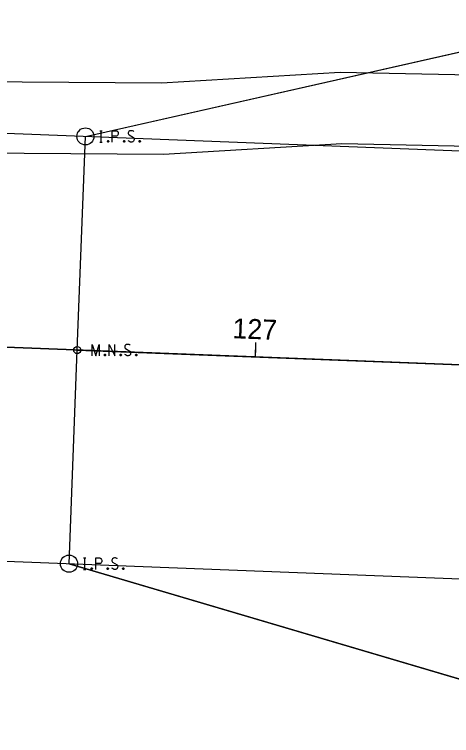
# Model space of a CAD drawing. Extents: x 2003596 to 2006933, y 570827 to 573780.
# Drawn here: x 2005400.5 to 2005461.8, y 572566.7 to 572667.9 of the extents above; entities that cross this region are included whole.
import ezdxf

# ---------------------------------------------------------------- set-up
doc = ezdxf.new("R2010")
doc.units = 0
for name, color, linetype in [('DT_X_Contour_Major', 7, 'Continuous'), ('DT_X_Spot_Elev', 7, 'Continuous'), ('GE_X_Alignment', 7, 'Continuous'), ('GE_X_Alignment_100_Stations', 7, 'Continuous'), ('GE_X_Alignment_500_Stations', 7, 'Continuous'), ('RW_X_CL', 7, 'Continuous'), ('RW_X_Esmt_SH', 7, 'Continuous'), ('SV_P_Mon_Cells_Set', 7, 'Continuous'), ('UT_X_Overhead_Electric', 7, 'Continuous'), ('UT_X_Overhead_Telecom', 7, 'Continuous'), ('UT_X_Telecom', 7, 'Continuous')]:
    doc.layers.add(name, color=color, linetype=linetype)

msp = doc.modelspace()

# ---------------------------------------------------------------- linework, layer by layer
at = {"layer": 'DT_X_Contour_Major'}
for points in [[(2005411.36, 572620.02), (2005411.36, 572621.62), (2005411.87, 572620.02), (2005412.36, 572621.62), (2005412.36, 572620.02)], [(2005413.73, 572620.02), (2005413.73, 572621.62), (2005414.56, 572620.02), (2005414.56, 572621.62)], [(2005416.71, 572621.51), (2005416.69, 572621.53), (2005416.65, 572621.56), (2005416.56, 572621.6), (2005416.43, 572621.62), (2005416.35, 572621.62), (2005416.31, 572621.62), (2005416.17, 572621.58), (2005416.05, 572621.51), (2005415.97, 572621.41), (2005415.95, 572621.31), (2005415.95, 572621.23), (2005415.97, 572621.13), (2005416.06, 572621.04), (2005416.67, 572620.67), (2005416.72, 572620.62), (2005416.74, 572620.56), (2005416.76, 572620.49), (2005416.76, 572620.41), (2005416.75, 572620.34), (2005416.74, 572620.29), (2005416.72, 572620.22), (2005416.7, 572620.17), (2005416.68, 572620.14), (2005416.64, 572620.1), (2005416.61, 572620.07), (2005416.57, 572620.05), (2005416.53, 572620.04), (2005416.43, 572620.02), (2005416.28, 572620.02), (2005416.18, 572620.05), (2005416.04, 572620.14), (2005415.95, 572620.21)], [(2005413.13, 572620.24), (2005413.18, 572620.24), (2005413.22, 572620.21), (2005413.25, 572620.16), (2005413.25, 572620.1), (2005413.22, 572620.05), (2005413.18, 572620.02), (2005413.13, 572620.02), (2005413.09, 572620.05), (2005413.06, 572620.1), (2005413.06, 572620.16), (2005413.09, 572620.21), (2005413.13, 572620.24)], [(2005415.34, 572620.24), (2005415.4, 572620.24), (2005415.43, 572620.21), (2005415.46, 572620.16), (2005415.46, 572620.1), (2005415.43, 572620.05), (2005415.4, 572620.02), (2005415.34, 572620.02), (2005415.31, 572620.05), (2005415.28, 572620.1), (2005415.28, 572620.16), (2005415.31, 572620.21), (2005415.34, 572620.24)], [(2005417.53, 572620.24), (2005417.58, 572620.24), (2005417.61, 572620.21), (2005417.65, 572620.16), (2005417.65, 572620.1), (2005417.61, 572620.05), (2005417.58, 572620.02), (2005417.53, 572620.02), (2005417.49, 572620.05), (2005417.46, 572620.1), (2005417.46, 572620.16), (2005417.49, 572620.21), (2005417.53, 572620.24)]]:
    msp.add_lwpolyline(points, dxfattribs=at)
msp.add_circle((2005409.27, 572620.82), 0.497, dxfattribs=at)
at = {"layer": 'DT_X_Spot_Elev'}
for p, q in [((2005410.42, 572650.8), (2005464.45, 572663.01)), ((2005409.27, 572620.82), (2005410.42, 572650.8)), ((2005408.12, 572590.85), (2005409.27, 572620.82)), ((2005465.42, 572618.67), (2005409.27, 572620.82)), ((2005409.27, 572620.82), (2005465.42, 572618.67)), ((2005466.41, 572573.6), (2005408.12, 572590.85))]:
    msp.add_line(p, q, dxfattribs=at)
at = {"layer": 'GE_X_Alignment'}
msp.add_line((2005031.48, 572635.32), (2006023.62, 572597.25), dxfattribs=at)
at = {"layer": 'GE_X_Alignment_100_Stations'}
msp.add_line((2005434.25, 572619.86), (2005434.33, 572621.86), dxfattribs=at)
at = {"layer": 'GE_X_Alignment_500_Stations'}
msp.add_line((2005434.25, 572619.86), (2005434.3, 572621.06), dxfattribs=at)
at = {"layer": 'RW_X_CL'}
msp.add_line((2006023.62, 572597.25), (2005031.48, 572635.32), dxfattribs=at)
at = {"layer": 'RW_X_Esmt_SH'}
for p, q in [((2005034.78, 572665.22), (2006024.45, 572627.24)), ((2005409.27, 572620.82), (2005410.42, 572650.8)), ((2005408.12, 572590.85), (2005409.27, 572620.82)), ((2005028.18, 572605.42), (2006022.8, 572567.26))]:
    msp.add_line(p, q, dxfattribs=at)
at = {"layer": 'SV_P_Mon_Cells_Set'}
for points in [[(2005412.44, 572651.6), (2005412.79, 572651.6)], [(2005412.62, 572650), (2005412.62, 572651.6)], [(2005414.18, 572650), (2005414.18, 572651.6), (2005414.71, 572651.6), (2005414.77, 572651.59), (2005414.85, 572651.57), (2005414.88, 572651.54), (2005414.91, 572651.51), (2005414.96, 572651.45), (2005414.99, 572651.39), (2005415.01, 572651.29), (2005415.01, 572651.14), (2005415, 572651.09), (2005414.98, 572651.01), (2005414.93, 572650.92), (2005414.89, 572650.88), (2005414.86, 572650.86), (2005414.8, 572650.83), (2005414.71, 572650.82), (2005414.18, 572650.82)], [(2005417.19, 572651.49), (2005417.17, 572651.51), (2005417.14, 572651.54), (2005417.04, 572651.58), (2005416.92, 572651.6), (2005416.83, 572651.6), (2005416.8, 572651.6), (2005416.65, 572651.57), (2005416.53, 572651.49), (2005416.45, 572651.39), (2005416.43, 572651.29), (2005416.43, 572651.21), (2005416.45, 572651.11), (2005416.54, 572651.02), (2005417.15, 572650.65), (2005417.2, 572650.6), (2005417.23, 572650.54), (2005417.25, 572650.47), (2005417.25, 572650.39), (2005417.24, 572650.32), (2005417.23, 572650.27), (2005417.2, 572650.2), (2005417.18, 572650.15), (2005417.16, 572650.12), (2005417.13, 572650.08), (2005417.09, 572650.05), (2005417.05, 572650.03), (2005417.02, 572650.02), (2005416.92, 572650), (2005416.76, 572650), (2005416.66, 572650.03), (2005416.52, 572650.12), (2005416.43, 572650.19)], [(2005413.58, 572650.22), (2005413.63, 572650.22), (2005413.67, 572650.19), (2005413.7, 572650.14), (2005413.7, 572650.08), (2005413.67, 572650.03), (2005413.63, 572650), (2005413.58, 572650), (2005413.54, 572650.03), (2005413.51, 572650.08), (2005413.51, 572650.14), (2005413.54, 572650.19), (2005413.58, 572650.22)], [(2005415.83, 572650.22), (2005415.88, 572650.22), (2005415.91, 572650.19), (2005415.95, 572650.14), (2005415.95, 572650.08), (2005415.91, 572650.03), (2005415.88, 572650), (2005415.83, 572650), (2005415.79, 572650.03), (2005415.76, 572650.08), (2005415.76, 572650.14), (2005415.79, 572650.19), (2005415.83, 572650.22)], [(2005418.01, 572650.22), (2005418.06, 572650.22), (2005418.1, 572650.19), (2005418.13, 572650.14), (2005418.13, 572650.08), (2005418.1, 572650.03), (2005418.06, 572650), (2005418.01, 572650), (2005417.98, 572650.03), (2005417.94, 572650.08), (2005417.94, 572650.14), (2005417.98, 572650.19), (2005418.01, 572650.22)], [(2005412.44, 572650), (2005412.79, 572650)], [(2005410.14, 572591.65), (2005410.49, 572591.65)], [(2005410.32, 572590.05), (2005410.32, 572591.65)], [(2005411.88, 572590.05), (2005411.88, 572591.65), (2005412.41, 572591.65), (2005412.47, 572591.63), (2005412.54, 572591.61), (2005412.58, 572591.58), (2005412.61, 572591.56), (2005412.65, 572591.5), (2005412.69, 572591.43), (2005412.71, 572591.33), (2005412.71, 572591.18), (2005412.7, 572591.13), (2005412.68, 572591.05), (2005412.63, 572590.97), (2005412.59, 572590.93), (2005412.56, 572590.9), (2005412.5, 572590.88), (2005412.41, 572590.87), (2005411.88, 572590.87)], [(2005414.89, 572591.53), (2005414.87, 572591.56), (2005414.84, 572591.58), (2005414.74, 572591.62), (2005414.62, 572591.65), (2005414.53, 572591.65), (2005414.5, 572591.65), (2005414.35, 572591.61), (2005414.23, 572591.53), (2005414.15, 572591.43), (2005414.13, 572591.33), (2005414.13, 572591.26), (2005414.15, 572591.16), (2005414.24, 572591.07), (2005414.85, 572590.69), (2005414.9, 572590.64), (2005414.93, 572590.59), (2005414.95, 572590.51), (2005414.95, 572590.44), (2005414.94, 572590.36), (2005414.93, 572590.31), (2005414.9, 572590.25), (2005414.88, 572590.2), (2005414.86, 572590.16), (2005414.83, 572590.12), (2005414.79, 572590.1), (2005414.75, 572590.07), (2005414.72, 572590.06), (2005414.62, 572590.05), (2005414.46, 572590.05), (2005414.36, 572590.07), (2005414.22, 572590.16), (2005414.13, 572590.24)], [(2005410.14, 572590.05), (2005410.49, 572590.05)], [(2005411.28, 572590.26), (2005411.33, 572590.26), (2005411.37, 572590.24), (2005411.4, 572590.19), (2005411.4, 572590.12), (2005411.37, 572590.07), (2005411.33, 572590.05), (2005411.28, 572590.05), (2005411.24, 572590.07), (2005411.21, 572590.12), (2005411.21, 572590.19), (2005411.24, 572590.24), (2005411.28, 572590.26)], [(2005413.53, 572590.26), (2005413.58, 572590.26), (2005413.61, 572590.24), (2005413.65, 572590.19), (2005413.65, 572590.12), (2005413.61, 572590.07), (2005413.58, 572590.05), (2005413.53, 572590.05), (2005413.49, 572590.07), (2005413.46, 572590.12), (2005413.46, 572590.19), (2005413.49, 572590.24), (2005413.53, 572590.26)], [(2005415.71, 572590.26), (2005415.76, 572590.26), (2005415.8, 572590.24), (2005415.83, 572590.19), (2005415.83, 572590.12), (2005415.8, 572590.07), (2005415.76, 572590.05), (2005415.71, 572590.05), (2005415.67, 572590.07), (2005415.64, 572590.12), (2005415.64, 572590.19), (2005415.67, 572590.24), (2005415.71, 572590.26)]]:
    msp.add_lwpolyline(points, dxfattribs=at)
for centre in [(2005410.42, 572650.8), (2005408.12, 572590.85)]:
    msp.add_circle(centre, 1.2, dxfattribs=at)
at = {"layer": 'UT_X_Overhead_Electric'}
for points in [[(2005410.42, 572650.8), (2005464.45, 572663.01), (2005486.13, 572667.91), (2005566.08, 572664.84), (2005635.26, 572642.17)], [(2005408.12, 572590.85), (2005466.41, 572573.6), (2005490.38, 572517.64), (2005565.32, 572514.76), (2005606.83, 572553.2), (2005652.37, 572566.46)]]:
    msp.add_lwpolyline(points, dxfattribs=at)
at = {"layer": 'UT_X_Overhead_Telecom'}
msp.add_lwpolyline([(2005410.42, 572650.8), (2005464.45, 572663.01), (2005486.13, 572667.91), (2005566.08, 572664.84), (2005635.26, 572642.17)], dxfattribs=at)
at = {"layer": 'UT_X_Telecom'}
for points in [[(2005147.76, 572660.26), (2005421.1, 572658.32), (2005446.17, 572659.8), (2005471.38, 572659.28), (2005497.09, 572658.54), (2005522.25, 572656.73), (2005547.24, 572652.92), (2005571.87, 572650.16), (2005596.85, 572649.37), (2005621.79, 572646.67), (2006021.03, 572631.61)], [(2005147.98, 572650.26), (2005421.36, 572648.31), (2005446.36, 572649.8), (2005471.14, 572649.29), (2005496.59, 572648.55), (2005521.14, 572646.78), (2005545.93, 572643), (2005571.15, 572640.18), (2005596.15, 572639.39), (2005621.06, 572636.69), (2006021.19, 572621.6)]]:
    msp.add_lwpolyline(points, dxfattribs=at)

# ---------------------------------------------------------------- texts
at = {"layer": 'GE_X_Alignment_100_Stations'}
msp.add_text('127', height=2.8, rotation=357.8026, dxfattribs=at).set_placement((2005431.01, 572622.49))

doc.saveas('drawing.dxf')
